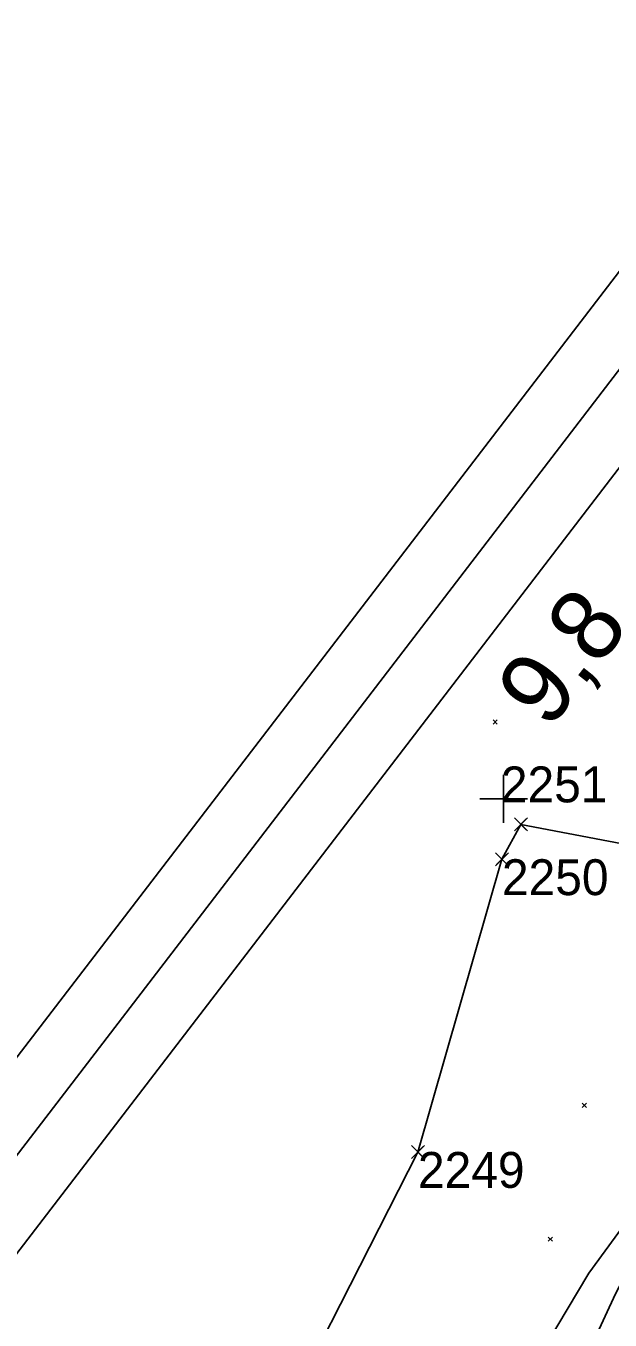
# Model space of a CAD drawing. Extents: x -866402 to -860377, y -1041908 to -1038598.
# Drawn here: x -862540 to -862491.1, y -1039343.6 to -1039235.4 of the extents above; entities that cross this region are included whole.
import ezdxf

# ---------------------------------------------------------------- set-up
doc = ezdxf.new("R2010")
doc.units = 0
for name, color, linetype in [('SZDC', 7, 'Continuous'), ('Vrstva 1', 7, 'Continuous'), ('Vrstva 49', 7, 'Continuous'), ('Vrstva 5', 7, 'Continuous'), ('Vrstva 60', 7, 'Continuous'), ('Vrstva 7', 7, 'Continuous')]:
    doc.layers.add(name, color=color, linetype=linetype)

msp = doc.modelspace()

# ---------------------------------------------------------------- linework, layer by layer
at = {"layer": 'SZDC'}
msp.add_lwpolyline([(-862521.71, -1039358.08), (-862507.17, -1039329.53), (-862500.14, -1039305.05), (-862498.55, -1039302.13), (-862487.25, -1039304.3), (-862484.62, -1039297.79), (-862467.38, -1039281.45), (-862436.33, -1039256.55), (-862366.3, -1039227.38), (-862303.99, -1039214.35), (-862283.48, -1039211.79), (-862297.66, -1039191.42), (-862263.73, -1039211.26), (-862253.31, -1039214.94), (-862234.51, -1039218.03), (-862199.37, -1039224.74)], dxfattribs=at)
at = {"layer": 'Vrstva 1'}
for points in [[(-862750.99, -1040083.46), (-861983.98, -1039083.83), (-862219.6, -1038903.04), (-862986.61, -1039902.67)], [(-862979.6, -1039901.75), (-862218.68, -1038910.05), (-861990.99, -1039084.75), (-862751.92, -1040076.45)], [(-862752.84, -1040069.45), (-862122.79, -1039248.31), (-862342.55, -1039079.69), (-862972.6, -1039900.83)], [(-862972.6, -1039900.83), (-862342.55, -1039079.69), (-862122.79, -1039248.31), (-862752.84, -1040069.45)]]:
    msp.add_lwpolyline(points, close=True, dxfattribs=at)
at = {"layer": 'Vrstva 49'}
for p, q in [((-862500.88, -1039293.4), (-862500.53, -1039293.76)), ((-862500.88, -1039293.76), (-862500.53, -1039293.4)), ((-862493.43, -1039325.45), (-862493.07, -1039325.8)), ((-862493.43, -1039325.8), (-862493.07, -1039325.45)), ((-862496.28, -1039336.65), (-862495.92, -1039337)), ((-862496.28, -1039337), (-862495.92, -1039336.65))]:
    msp.add_line(p, q, dxfattribs=at)
for points in [[(-862512.37, -1039384.39), (-862508.26, -1039369.44), (-862501.61, -1039354.29), (-862492.88, -1039339.66), (-862488.77, -1039334.06)], [(-862487.3, -1039335.01), (-862490.63, -1039341.38), (-862497.35, -1039355.91), (-862503.11, -1039370.37), (-862507.92, -1039385.92)]]:
    msp.add_lwpolyline(points, dxfattribs=at)
at = {"layer": 'Vrstva 5'}
for p, q in [((-862500, -1039298), (-862500, -1039302)), ((-862502, -1039300), (-862498, -1039300))]:
    msp.add_line(p, q, dxfattribs=at)
at = {"layer": 'Vrstva 60'}
for p, q in [((-862498.1, -1039302.58), (-862499.1, -1039301.58)), ((-862498.1, -1039301.68), (-862499.1, -1039302.68)), ((-862499, -1039302.58), (-862498, -1039301.58)), ((-862499, -1039301.68), (-862498, -1039302.68)), ((-862498.55, -1039302.13), (-862498.55, -1039302.13)), ((-862499.69, -1039305.5), (-862500.69, -1039304.5)), ((-862499.69, -1039304.6), (-862500.69, -1039305.6)), ((-862500.59, -1039305.5), (-862499.59, -1039304.5)), ((-862500.59, -1039304.6), (-862499.59, -1039305.6)), ((-862500.14, -1039305.05), (-862500.14, -1039305.05)), ((-862506.72, -1039329.98), (-862507.72, -1039328.98)), ((-862507.62, -1039329.98), (-862506.62, -1039328.98)), ((-862506.72, -1039329.08), (-862507.72, -1039330.08)), ((-862507.62, -1039329.08), (-862506.62, -1039330.08)), ((-862507.17, -1039329.53), (-862507.17, -1039329.53))]:
    msp.add_line(p, q, dxfattribs=at)

# ---------------------------------------------------------------- texts
for s, p in [('2251', (-862500.23, -1039300.29)), ('2250', (-862500.14, -1039308.05)), ('2249', (-862507.17, -1039332.53))]:
    msp.add_text(s, height=3, dxfattribs=at).set_placement(p)
at = {"layer": 'Vrstva 7'}
msp.add_text('9,8', height=6, rotation=51.9704, dxfattribs=at).set_placement((-862496.23, -1039294.32))

doc.saveas('drawing.dxf')
